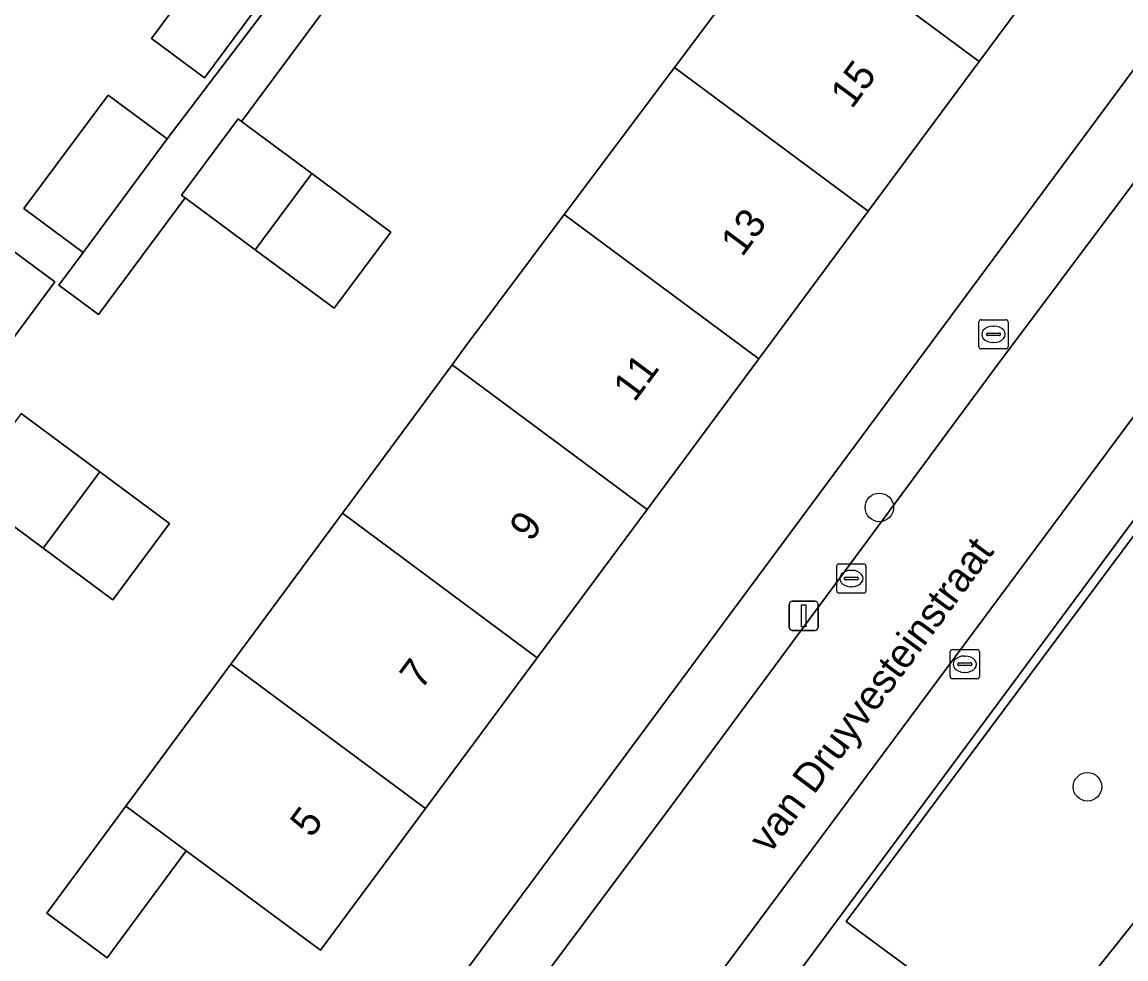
# Model space of a CAD drawing. Extents: x 160023 to 161302, y 384750 to 385707.
# Drawn here: x 160331.15 to 160368.97, y 385172.03 to 385204.12 of the extents above; entities that cross this region are included whole.
import ezdxf

# ---------------------------------------------------------------- set-up
doc = ezdxf.new("R2010")
doc.units = 0
for name, color, linetype in [('IMGEO_Boom', 7, 'Continuous'), ('IMGEO_Brandkraan', 7, 'Continuous'), ('IMGEO_Erf', 7, 'Continuous'), ('IMGEO_Groenvoorziening', 7, 'Continuous'), ('IMGEO_Kolk', 7, 'Continuous'), ('IMGEO_Lichtmast', 7, 'Continuous'), ('IMGEO_Openbare_ruimte_label', 7, 'Continuous'), ('IMGEO_Pand', 7, 'Continuous'), ('IMGEO_Pand_nummerreeks', 7, 'Continuous'), ('IMGEO_Parkeervlak_open', 7, 'Continuous'), ('IMGEO_Rijbaan_lokaal_open', 7, 'Continuous'), ('IMGEO_Voetpad_open', 7, 'Continuous')]:
    doc.layers.add(name, color=color, linetype=linetype)

msp = doc.modelspace()

# ---------------------------------------------------------------- linework, layer by layer
at = {"layer": 'IMGEO_Boom'}
for centre in [(160360.52, 385187.493), (160367.65, 385177.922)]:
    msp.add_circle(centre, 0.489, dxfattribs=at)
at = {"layer": 'IMGEO_Brandkraan'}
for p, q in [((160363.929, 385192.996), (160363.929, 385193.848)), ((160364.004, 385193.922), (160364.856, 385193.922)), ((160364.93, 385193.848), (160364.93, 385192.996)), ((160364.188, 385193.416), (160364.188, 385193.428)), ((160364.231, 385193.465), (160364.629, 385193.465)), ((160364.417, 385193.702), (160364.442, 385193.702)), ((160364.672, 385193.428), (160364.672, 385193.416)), ((160364.626, 385193.379), (160364.228, 385193.379)), ((160364.44, 385193.142), (160364.415, 385193.142)), ((160364.856, 385192.922), (160364.004, 385192.922))]:
    msp.add_line(p, q, dxfattribs=at)
for points in [[(160363.929, 385192.996), (160363.929, 385193.848)], [(160364.004, 385193.922), (160364.856, 385193.922)], [(160364.93, 385193.848), (160364.93, 385192.996)], [(160364.856, 385192.922), (160364.004, 385192.922)]]:
    msp.add_lwpolyline(points, dxfattribs=at)
for centre, radius, start, end in [((160364.006, 385193.846), 0.0765, 91.552, 178.448), ((160364.006, 385193.846), 0.0765, 91.552, 178.448), ((160364.854, 385193.846), 0.0765, 1.552, 88.448), ((160364.854, 385193.846), 0.0765, 1.552, 88.448), ((160364.228, 385193.425), 0.0403, 85.8775, 175.7526), ((160364.225, 385193.415), 0.0366, 178.938, 274.7102), ((160364.629, 385193.422), 0.043, 264.8664, 352.4533), ((160364.633, 385193.427), 0.0386, 1.7309, 96.639), ((160364.006, 385192.998), 0.0765, 181.552, 268.448), ((160364.006, 385192.998), 0.0765, 181.552, 268.448), ((160364.854, 385192.998), 0.0765, 271.552, 358.448), ((160364.854, 385192.998), 0.0765, 271.552, 358.448)]:
    msp.add_arc(centre, radius, start, end, dxfattribs=at)
for centre, major_axis, ratio, start_param, end_param in [((160364.416, 385193.422), (-0.387, 0.002), 0.722429, 4.712389, 7.853982), ((160364.441, 385193.422), (-0.39, 0.002), 0.717154, 1.570796, 4.712389)]:
    msp.add_ellipse(centre, major_axis=major_axis, ratio=ratio, start_param=start_param, end_param=end_param, dxfattribs=at)
at = {"layer": 'IMGEO_Erf'}
for points in [[(160325.028, 385142.851), (160374.618, 385209.767)], [(160344.225, 385208.216), (160338.669, 385200.715), (160341.077, 385198.929), (160343.783, 385196.924), (160341.848, 385194.314), (160339.142, 385196.319), (160336.734, 385198.103), (160333.772, 385194.104), (160332.416, 385195.109), (160333.245, 385196.228), (160331.217, 385197.732), (160334.098, 385201.62), (160336.127, 385200.117), (160341.701, 385207.476)], [(160367.649, 385207.769), (160363.942, 385202.768), (160360.141, 385197.642), (160356.391, 385192.582), (160352.566, 385187.423), (160348.802, 385182.345), (160344.971, 385177.177), (160341.375, 385172.327), (160336.776, 385175.727), (160334.066, 385172.062), (160331.999, 385173.591), (160334.71, 385177.259), (160338.303, 385182.119), (160342.127, 385187.292), (160342.457, 385187.738), (160345.885, 385192.375), (160346.326, 385192.988), (160349.724, 385197.524), (160353.5, 385202.564), (160357.327, 385207.672)], [(160331.122, 385190.705), (160333.815, 385188.709), (160336.203, 385186.939), (160334.264, 385184.322), (160331.876, 385186.092), (160329.274, 385188.021)]]:
    msp.add_lwpolyline(points, dxfattribs=at)
for points in [[(160337.397, 385202.213), (160335.582, 385203.559), (160337.934, 385206.732), (160339.749, 385205.386)], [(160332.271, 385195.216), (160329.922, 385192.045), (160328.021, 385193.453), (160330.37, 385196.624)]]:
    msp.add_lwpolyline(points, close=True, dxfattribs=at)
at = {"layer": 'IMGEO_Groenvoorziening'}
msp.add_lwpolyline([(160376.389, 385182.23), (160370.176, 385186.877), (160369.737, 385187.204), (160359.382, 385173.302), (160359.884, 385172.928), (160365.601, 385168.714)], close=True, dxfattribs=at)
at = {"layer": 'IMGEO_Kolk'}
for p, q in [((160359.061, 385184.631), (160359.061, 385185.483)), ((160359.136, 385185.557), (160359.988, 385185.557)), ((160360.062, 385185.483), (160360.062, 385184.631)), ((160359.363, 385185.1), (160359.761, 385185.1)), ((160359.549, 385185.337), (160359.574, 385185.337)), ((160359.32, 385185.051), (160359.32, 385185.063)), ((160359.758, 385185.014), (160359.36, 385185.014)), ((160359.572, 385184.777), (160359.547, 385184.777)), ((160359.804, 385185.063), (160359.804, 385185.051)), ((160359.988, 385184.557), (160359.136, 385184.557)), ((160362.946, 385181.695), (160362.946, 385182.547)), ((160363.021, 385182.621), (160363.873, 385182.621)), ((160363.947, 385182.547), (160363.947, 385181.695)), ((160363.205, 385182.115), (160363.205, 385182.127)), ((160363.643, 385182.078), (160363.245, 385182.078)), ((160363.248, 385182.164), (160363.646, 385182.164)), ((160363.434, 385182.401), (160363.459, 385182.401)), ((160363.689, 385182.127), (160363.689, 385182.115)), ((160363.457, 385181.841), (160363.432, 385181.841)), ((160363.873, 385181.621), (160363.021, 385181.621))]:
    msp.add_line(p, q, dxfattribs=at)
for points in [[(160359.061, 385184.631), (160359.061, 385185.483)], [(160359.136, 385185.557), (160359.988, 385185.557)], [(160360.062, 385185.483), (160360.062, 385184.631)], [(160359.988, 385184.557), (160359.136, 385184.557)], [(160362.946, 385181.695), (160362.946, 385182.547)], [(160363.021, 385182.621), (160363.873, 385182.621)], [(160363.947, 385182.547), (160363.947, 385181.695)], [(160363.873, 385181.621), (160363.021, 385181.621)]]:
    msp.add_lwpolyline(points, dxfattribs=at)
for centre, radius, start, end in [((160359.138, 385185.481), 0.0765, 91.552, 178.448), ((160359.138, 385185.481), 0.0765, 91.552, 178.448), ((160359.986, 385185.481), 0.0765, 1.552, 88.448), ((160359.986, 385185.481), 0.0765, 1.552, 88.448), ((160359.36, 385185.06), 0.0403, 85.8775, 175.7526), ((160359.765, 385185.062), 0.0386, 1.7309, 96.639), ((160359.357, 385185.05), 0.0366, 178.938, 274.7102), ((160359.761, 385185.057), 0.043, 264.8664, 352.4533), ((160359.138, 385184.633), 0.0765, 181.552, 268.448), ((160359.138, 385184.633), 0.0765, 181.552, 268.448), ((160359.986, 385184.633), 0.0765, 271.552, 358.448), ((160359.986, 385184.633), 0.0765, 271.552, 358.448), ((160363.023, 385182.545), 0.0765, 91.552, 178.448), ((160363.023, 385182.545), 0.0765, 91.552, 178.448), ((160363.871, 385182.545), 0.0765, 1.552, 88.448), ((160363.871, 385182.545), 0.0765, 1.552, 88.448), ((160363.245, 385182.124), 0.0403, 85.8775, 175.7526), ((160363.242, 385182.114), 0.0366, 178.938, 274.7102), ((160363.646, 385182.121), 0.043, 264.8664, 352.4533), ((160363.65, 385182.126), 0.0386, 1.7309, 96.639), ((160363.023, 385181.697), 0.0765, 181.552, 268.448), ((160363.023, 385181.697), 0.0765, 181.552, 268.448), ((160363.871, 385181.697), 0.0765, 271.552, 358.448), ((160363.871, 385181.697), 0.0765, 271.552, 358.448)]:
    msp.add_arc(centre, radius, start, end, dxfattribs=at)
for centre, major_axis, ratio, start_param, end_param in [((160359.548, 385185.057), (-0.387, 0.002), 0.722429, 4.712389, 7.853982), ((160359.573, 385185.057), (-0.39, 0.002), 0.717154, 1.570796, 4.712389), ((160363.433, 385182.121), (-0.387, 0.002), 0.722429, 4.712389, 7.853982), ((160363.458, 385182.121), (-0.39, 0.002), 0.717154, 1.570796, 4.712389)]:
    msp.add_ellipse(centre, major_axis=major_axis, ratio=ratio, start_param=start_param, end_param=end_param, dxfattribs=at)
at = {"layer": 'IMGEO_Lichtmast'}
for p, q in [((160357.434, 385183.381), (160357.434, 385184.181)), ((160357.434, 385184.181), (160357.434, 385183.381)), ((160357.534, 385184.281), (160358.324, 385184.281)), ((160358.324, 385184.281), (160357.534, 385184.281)), ((160358.424, 385184.181), (160358.424, 385183.381)), ((160358.424, 385183.381), (160358.424, 385184.181)), ((160358.324, 385183.281), (160357.534, 385183.281)), ((160357.534, 385183.281), (160358.324, 385183.281))]:
    msp.add_line(p, q, dxfattribs=at)
msp.add_lwpolyline([(160357.854, 385184.156), (160358.004, 385184.156), (160358.004, 385183.406), (160357.854, 385183.406), (160357.854, 385184.156)], dxfattribs=at)
for centre, start, end in [((160357.534, 385184.181), 90, 180), ((160357.534, 385184.181), 90, 180), ((160358.324, 385184.181), 0, 90), ((160358.324, 385184.181), 360, 90), ((160357.534, 385183.381), 180, 270), ((160357.534, 385183.381), 180, 270), ((160358.324, 385183.381), 270, 0), ((160358.324, 385183.381), 270, 0)]:
    msp.add_arc(centre, 0.1, start, end, dxfattribs=at)
at = {"layer": 'IMGEO_Pand'}
for points in [[(160363.942, 385202.768), (160367.649, 385207.769), (160361.059, 385212.654), (160357.327, 385207.672)], [(160357.327, 385207.672), (160353.5, 385202.564), (160360.141, 385197.642), (160363.942, 385202.768)], [(160335.582, 385203.559), (160337.397, 385202.213), (160339.749, 385205.386), (160337.934, 385206.732)], [(160356.391, 385192.582), (160360.141, 385197.642), (160353.5, 385202.564), (160349.724, 385197.524)], [(160331.217, 385197.732), (160333.245, 385196.228), (160336.127, 385200.117), (160334.098, 385201.62)], [(160338.669, 385200.715), (160338.55, 385200.803), (160336.615, 385198.192), (160336.734, 385198.103), (160339.142, 385196.319), (160341.077, 385198.929)], [(160341.077, 385198.929), (160339.142, 385196.319), (160341.848, 385194.314), (160343.783, 385196.924)], [(160349.724, 385197.524), (160346.326, 385192.988), (160345.885, 385192.375), (160352.566, 385187.423), (160356.391, 385192.582)], [(160332.271, 385195.216), (160330.37, 385196.624), (160328.021, 385193.453), (160329.922, 385192.045)], [(160345.885, 385192.375), (160342.457, 385187.738), (160342.127, 385187.292), (160348.802, 385182.345), (160352.566, 385187.423)], [(160331.088, 385190.659), (160329.182, 385188.089), (160329.274, 385188.021), (160331.876, 385186.092), (160333.815, 385188.709), (160331.122, 385190.705)], [(160333.815, 385188.709), (160331.876, 385186.092), (160334.264, 385184.322), (160336.203, 385186.939)], [(160344.971, 385177.177), (160348.802, 385182.345), (160342.127, 385187.292), (160338.303, 385182.119)], [(160344.971, 385177.177), (160338.303, 385182.119), (160334.71, 385177.259), (160336.776, 385175.727), (160341.375, 385172.327)], [(160336.776, 385175.727), (160334.71, 385177.259), (160331.999, 385173.591), (160334.066, 385172.062)]]:
    msp.add_lwpolyline(points, close=True, dxfattribs=at)
at = {"layer": 'IMGEO_Parkeervlak_open'}
for points in [[(160382.334, 385208.244), (160338.119, 385148.731), (160337.805, 385148.31)], [(160341.816, 385150.156), (160342.909, 385151.604), (160351.745, 385163.449), (160367.915, 385185.269), (160372.205, 385191.078), (160381.943, 385204.063)]]:
    msp.add_lwpolyline(points, dxfattribs=at)
at = {"layer": 'IMGEO_Rijbaan_lokaal_open'}
for points in [[(160389.791, 385226.135), (160376.256, 385207.995), (160364.435, 385192.191), (160353.385, 385177.257), (160342.6, 385162.805), (160333.448, 385150.481), (160328.079, 385143.273)], [(160332.549, 385141.299), (160337.805, 385148.31), (160338.119, 385148.731), (160382.334, 385208.244)]]:
    msp.add_lwpolyline(points, dxfattribs=at)
at = {"layer": 'IMGEO_Voetpad_open'}
for points in [[(160328.079, 385143.273), (160333.448, 385150.481), (160342.6, 385162.805), (160353.385, 385177.257), (160364.435, 385192.191), (160376.256, 385207.995), (160389.791, 385226.135)], [(160374.618, 385209.767), (160325.028, 385142.851)], [(160341.701, 385207.476), (160336.127, 385200.117), (160333.245, 385196.228), (160332.416, 385195.109), (160333.772, 385194.104), (160336.734, 385198.103), (160336.615, 385198.192), (160338.55, 385200.803), (160338.669, 385200.715), (160344.225, 385208.216)], [(160381.943, 385204.063), (160372.205, 385191.078), (160367.915, 385185.269), (160351.745, 385163.449), (160342.909, 385151.604), (160341.816, 385150.156)]]:
    msp.add_lwpolyline(points, dxfattribs=at)
msp.add_lwpolyline([(160365.601, 385168.714), (160359.884, 385172.928), (160359.382, 385173.302), (160369.737, 385187.204), (160370.176, 385186.877), (160376.389, 385182.23)], close=True, dxfattribs=at)

# ---------------------------------------------------------------- texts
at = {"layer": 'IMGEO_Openbare_ruimte_label'}
msp.add_text('van Druyvesteinstraat', height=1, rotation=53.4166, dxfattribs=at).set_placement((160356.769, 385175.595))
at = {"layer": 'IMGEO_Pand_nummerreeks'}
for s, rotation, p in [('15', 53.4494, (160359.575, 385201.11)), ('13', 53.4494, (160355.818, 385196.042)), ('11', 53.4512, (160352.129, 385191.065)), ('9', 53.4512, (160348.579, 385186.276)), ('7', 53.4494, (160344.822, 385181.209)), ('5', 53.4494, (160341.065, 385176.141))]:
    msp.add_text(s, height=1, rotation=rotation, dxfattribs=at).set_placement(p)

doc.saveas('drawing.dxf')
